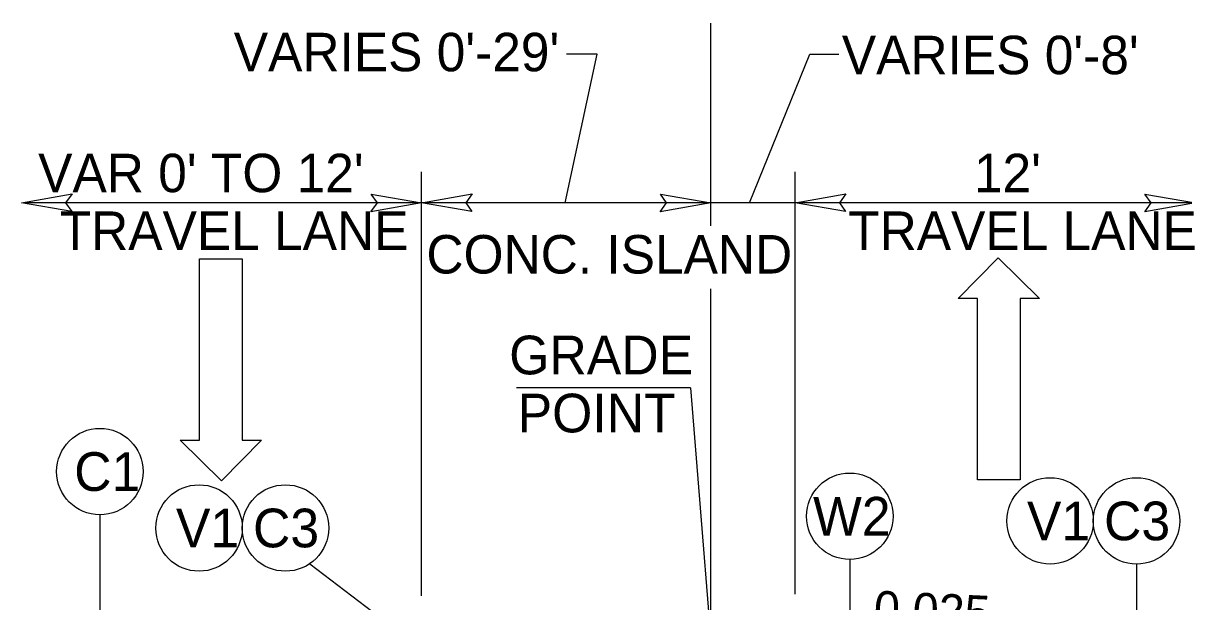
# Model space of a CAD drawing. Extents: x 2176156 to 2177167, y 76401 to 76644.
# Drawn here: x 2176800.9 to 2176835.7, y 76566.67 to 76584.02 of the extents above; entities that cross this region are included whole.
import ezdxf

# ---------------------------------------------------------------- set-up
doc = ezdxf.new("R2010")
doc.units = 0
for name, color, linetype in [('Exist Structure Minor Culvert Topo', 7, 'Continuous'), ('Exist Structure Minor Drop Inlet', 7, 'Continuous'), ('Exist Utilities Other Pole CELL', 7, 'Continuous'), ('Old_Level_1', 7, 'Continuous'), ('Old_Level_3', 7, 'Continuous'), ('Prop North Arrow NAD83 for Plan Sheets CELL', 7, 'Continuous')]:
    doc.layers.add(name, color=color, linetype=linetype)

msp = doc.modelspace()

# ---------------------------------------------------------------- linework, layer by layer
at = {"layer": 'Exist Structure Minor Drop Inlet'}
for p, q in [((2176806.184, 76571.517), (2176806.184, 76576.949)), ((2176806.184, 76576.949), (2176807.464, 76576.949)), ((2176807.464, 76576.949), (2176807.464, 76571.517)), ((2176828.934, 76575.76), (2176830.137, 76576.983)), ((2176830.137, 76576.983), (2176831.379, 76575.76)), ((2176829.516, 76575.76), (2176828.934, 76575.76)), ((2176829.516, 76570.328), (2176829.516, 76575.76)), ((2176831.379, 76575.76), (2176830.797, 76575.76)), ((2176830.797, 76575.76), (2176830.797, 76570.328)), ((2176806.844, 76570.295), (2176805.602, 76571.517)), ((2176805.602, 76571.517), (2176806.184, 76571.517)), ((2176808.046, 76571.517), (2176806.844, 76570.295)), ((2176807.464, 76571.517), (2176808.046, 76571.517)), ((2176830.797, 76570.328), (2176829.516, 76570.328))]:
    msp.add_line(p, q, dxfattribs=at)
at = {"layer": 'Old_Level_1'}
for points in [[(2176802.353, 76578.375), (2176800.844, 76578.635), (2176802.362, 76578.904), (2176802.169, 76578.635)], [(2176811.334, 76578.895), (2176812.844, 76578.635), (2176811.326, 76578.367), (2176811.518, 76578.635)], [(2176814.353, 76578.375), (2176812.844, 76578.635), (2176814.362, 76578.904), (2176814.169, 76578.635)], [(2176820.009, 76578.895), (2176821.519, 76578.635), (2176820.001, 76578.367), (2176820.194, 76578.635)], [(2176825.558, 76578.375), (2176824.049, 76578.635), (2176825.567, 76578.904), (2176825.374, 76578.635)], [(2176834.539, 76578.895), (2176836.049, 76578.635), (2176834.531, 76578.367), (2176834.724, 76578.635)]]:
    msp.add_lwpolyline(points, close=True, dxfattribs=at)
at = {"layer": 'Old_Level_3'}
for p, q in [((2176821.519, 76579.434), (2176821.519, 76584.018)), ((2176817.146, 76578.635), (2176818.114, 76583.095)), ((2176818.114, 76583.095), (2176817.191, 76583.095)), ((2176822.682, 76578.635), (2176824.489, 76583.095)), ((2176824.489, 76583.095), (2176825.354, 76583.095)), ((2176812.844, 76566.848), (2176812.844, 76579.563)), ((2176824.049, 76566.898), (2176824.049, 76579.563)), ((2176821.519, 76577.947), (2176821.519, 76579.434)), ((2176812.844, 76578.635), (2176800.95, 76578.635)), ((2176824.049, 76578.635), (2176812.844, 76578.635)), ((2176836.049, 76578.635), (2176824.049, 76578.635)), ((2176821.519, 76557.603), (2176821.519, 76576.05))]:
    msp.add_line(p, q, dxfattribs=at)
at = {"layer": 'Prop North Arrow NAD83 for Plan Sheets CELL'}
for p, q in [((2176820.911, 76573.085), (2176815.693, 76573.085)), ((2176820.911, 76573.085), (2176821.519, 76565.542)), ((2176803.195, 76569.278), (2176803.195, 76564.975)), ((2176809.493, 76567.812), (2176812.641, 76565.416)), ((2176825.686, 76567.938), (2176825.686, 76565.285)), ((2176834.285, 76567.798), (2176834.285, 76565.144))]:
    msp.add_line(p, q, dxfattribs=at)
for centre in [(2176803.195, 76570.574), (2176825.686, 76569.234), (2176806.17, 76568.882), (2176808.762, 76568.882), (2176831.693, 76569.094), (2176834.285, 76569.094)]:
    msp.add_circle(centre, 1.296, dxfattribs=at)

# ---------------------------------------------------------------- texts
at = {"layer": 'Exist Structure Minor Culvert Topo'}
for s, height, p in [("VARIES 0'-29'", 1.15334, (2176807.212, 76582.577)), ("VARIES 0'-8'", 1.15334, (2176825.448, 76582.489)), ("VAR 0' TO 12'", 1.15334, (2176801.346, 76578.951)), ("12'", 1.1533, (2176829.409, 76578.951)), ('TRAVEL LANE', 1.15334, (2176801.992, 76577.221)), ('TRAVEL LANE', 1.15334, (2176825.639, 76577.221)), ('CONC. ISLAND', 1.15334, (2176812.989, 76576.513))]:
    msp.add_text(s, height=height, dxfattribs=at).set_placement(p)
at = {"layer": 'Exist Utilities Other Pole CELL'}
msp.add_text('0.025', height=1.0429, rotation=357.3324, dxfattribs=at).set_placement((2176826.389, 76565.963))
at = {"layer": 'Prop North Arrow NAD83 for Plan Sheets CELL'}
for s, rotation, p in [('GRADE', 0.0002, (2176815.471, 76573.489)), ('POINT', 0.0002, (2176815.724, 76571.749)), ('C1', 0.0003, (2176802.426, 76569.994)), ('W2', 0.0003, (2176824.583, 76568.654)), ('V1', 0.0003, (2176805.477, 76568.302)), ('C3', 0.0003, (2176807.789, 76568.302)), ('V1', 0.0003, (2176830.999, 76568.514)), ('C3', 0.0003, (2176833.312, 76568.514))]:
    msp.add_text(s, height=1.16, rotation=rotation, dxfattribs=at).set_placement(p)

doc.saveas('drawing.dxf')
